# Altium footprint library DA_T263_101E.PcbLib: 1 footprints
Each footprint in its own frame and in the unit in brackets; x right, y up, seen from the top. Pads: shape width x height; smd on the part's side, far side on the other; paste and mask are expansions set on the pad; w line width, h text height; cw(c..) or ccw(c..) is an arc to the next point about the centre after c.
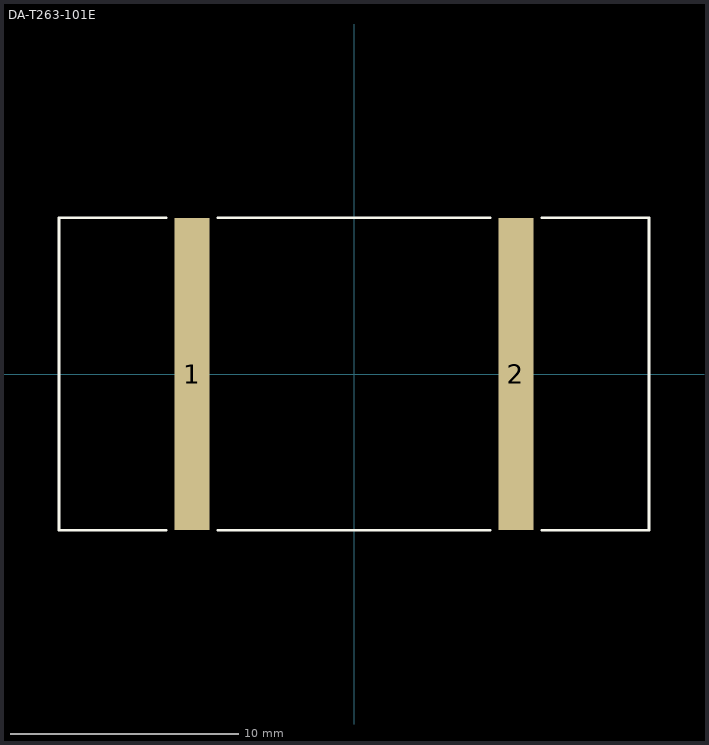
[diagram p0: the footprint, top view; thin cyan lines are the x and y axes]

## DA-T263-101E [mil] "D2PAK Heatsink"
pads (2):
  rect 60x540 smd: 1(-280,0) 2(280,0)
Top Overlay:
  lines w5: -325,-270 -510,-270 -510,270 -325,270 ; -235,-270 235,-270 ; -235,270 235,270 ; 325,-270 510,-270 510,270 325,270
M5 Assembly Top:
  text ".Designator" at -60,-20 h40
